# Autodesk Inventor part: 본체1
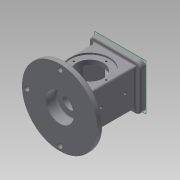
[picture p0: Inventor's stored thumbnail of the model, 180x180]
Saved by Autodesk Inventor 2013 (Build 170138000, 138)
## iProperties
Created: 2019-08
Part Number: 본체1
Material: 일반
Document SubType Name: Modeling
Designer: Administrator
Density: 1 g/cm^3
Author: Administrator
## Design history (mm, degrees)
sketch "스케치6"
  geometry: C1 r 67.5 at (0, 0); 1 further point
  constraints: 1 centre point, 1 coincident
  dimensions: "d14" = 135 diameter of C1
extrude "돌출4" new body sketch "스케치6" distance "d15" = 10; taper "d16" = 0 deg
sketch "스케치7"
  geometry: L1 (-37, -33)-(37, -33); L2 (37, -33)-(37, 33); L3 (37, 33)-(-37, 33); L4 (-37, 33)-(-37, -33); L5 (-37, -33)-(37, 33); L6 (37, -33)-(-37, 33); C1 r 67.5 at (0, 0) reference
  constraints: 12 end point, 2 midpoint, 2 parallel, 1 horizontal, 1 perpendicular
  dimensions: "d17" = 74 distance of L3.end L2.end; "d18" = 66 distance of L2.end L1.end
extrude "돌출5" join sketch "스케치7" distance "d19" = 88; taper "d20" = 0 deg
sketch "스케치8"
  geometry: L1 (-46, -41)-(46, -41); L2 (46, -41)-(46, 41); L3 (46, 41)-(-46, 41); L4 (-46, 41)-(-46, -41); L5 (-46, -41)-(46, 41); L6 (46, -41)-(-46, 41); 1 further point
  constraints: 12 end point, 2 midpoint, 2 parallel, 1 horizontal, 1 perpendicular
  dimensions: "d21" = 92 distance of L3.end L2.end; "d22" = 82 distance of L2.end L1.end
extrude "돌출6" join sketch "스케치8" distance "d23" = 10; taper "d24" = 0 deg
sketch "스케치9"
  geometry: L1 (37, -10)-(37, 44); C1 r 35 at (37, 44)
  constraints: 2 end point, 1 centre point, 1 coincident, 1 vertical
  dimensions: "d25" = 54 distance of L1.start L1.end; "d26" = 70 diameter of C1
extrude "돌출7" cut sketch "스케치9" distance "d27" = 3; taper "d28" = 0 deg
sketch "스케치10"
  geometry: C1 r 35 at (0, 0) reference; C2 r 24 at (0, 0); 1 further point
  constraints: 1 centre point, 1 coincident
  dimensions: "d29" = 48 diameter of C2
extrude "돌출8" cut sketch "스케치10" stored distance "d30" = 3; taper "d31" = 0 deg
sketch "스케치11"
  geometry: C1 r 24 at (37, 44) reference; C2 r 35 at (37, 44); 1 further point
  constraints: 1 centre point, 1 coincident
  dimensions: "d32" = 70 diameter of C2
extrude "돌출9" cut sketch "스케치11" distance "d33" = 3; taper "d34" = 0 deg
sketch "스케치12"
  geometry: L1 (-26, -26)-(26, -26); L2 (26, -26)-(26, 26); L3 (26, 26)-(-26, 26); L4 (-26, 26)-(-26, -26); L5 (-26, -26)-(26, 26); L6 (26, -26)-(-26, 26); 1 further point
  constraints: 12 end point, 2 midpoint, 2 parallel, 1 horizontal, 1 perpendicular
  dimensions: "d35" = 52 distance of L3.end L2.end; "d36" = 52 distance of L2.end L1.end
extrude "돌출10" cut sketch "스케치12" distance "d37" = 8; taper "d38" = 0 deg
sketch "스케치13"
  geometry: L1 (-22, -22)-(22, -22); L2 (22, -22)-(22, 22); L3 (22, 22)-(-22, 22); L4 (-22, 22)-(-22, -22); L5 (-22, -22)-(22, 22); L6 (22, -22)-(-22, 22); 1 further point
  constraints: 12 end point, 2 midpoint, 2 parallel, 1 horizontal, 1 perpendicular
  dimensions: "d39" = 44 distance of L3.end L2.end; "d40" = 44 distance of L2.end L1.end
extrude "돌출11" cut sketch "스케치13" distance "d41" = 74; taper "d42" = 0 deg
sketch "스케치14"
  geometry: C1 r 67.5 at (0, 0) reference; C2 r 25 at (0, 0)
  constraints: 1 centre point, 1 coincident
  dimensions: "d43" = 50 diameter of C2
extrude "돌출12" cut sketch "스케치14" distance "d44" = 18; taper "d45" = 0 deg
sketch "스케치16"
  geometry: L1 (0, 0)-(0, 59); L2 (0, 0)-(-59, 0); L3 (0, 0)-(0, -59); C1 r 67.5 at (0, 0) reference; C2 r 4.5 at (0, 59); C3 r 4.5 at (-59, 0); C4 r 4.5 at (0, -59)
  constraints: 6 end point, 3 centre point, 3 coincident, 2 vertical, 1 horizontal
  dimensions: "d49" = 59 distance of L1.start L1.end; "d50" = 9 diameter of C2; "d54" = 59 distance of L1.start L2.end; "d55" = 9 diameter of C3; "d56" = 59 distance of L1.start L3.end; "d57" = 9 diameter of C4
extrude "돌출14" cut sketch "스케치16" distance "d58" = 18; taper "d59" = 0 deg
sketch "스케치17"
  geometry: C1 r 35 at (0, 0) reference; A1 r 29 centre (0, 0) between (0, 29) and (-29, 0); 3 further points
  constraints: 4 point on circle, 1 centre point, 1 coincident
  dimensions: "d61" = 58 diameter of A1
hole "구멍1" sketch "스케치17" at (0, 29), (-29, 0), (0, -29), (29, 0) diameter "d62" = 3.242; stored, may be unused: countersink angle "d66" = 90 deg, drill point angle "d68" = 118 deg; dims "d63" = 4, "d64" = 4, "d65" = 2, "d67" = 6
sketch "스케치18" dims "d69" = 58
  geometry: C1 r 35 at (0, 0) reference; C2 r 1.621 at (-29, 0) reference; C3 r 1.621 at (0, -29) reference; C4 r 1.621 at (29, 0) reference; 6 further points
  constraints: 4 coincident, 1 vertical alignment, 2 other
hole "구멍2" sketch "스케치18" at (0, 29), (-29, 0), (0, -29), (29, 0) diameter "d70" = 3.242; stored, may be unused: countersink angle "d74" = 90 deg, drill point angle "d76" = 118 deg; dims "d71" = 4, "d72" = 4, "d73" = 2, "d75" = 6
sketch "스케치19"
  geometry: L1 (26, 26)-(26, -26) reference; L2 (26, -26)-(-26, -26) reference; L3 (-26, -26)-(-26, 26) reference; L4 (-26, 26)-(26, 26) reference; L5 (-46, -41)-(46, -41) reference; L6 (46, -41)-(46, 41) reference; L7 (46, 41)-(-46, 41) reference; L8 (-46, 41)-(-46, -41) reference; 1 further point
sketch "스케치20"
  geometry: C1 r 25 at (0, 0) reference; C2 r 12.5 at (0, 0)
  constraints: 1 centre point, 1 coincident
  dimensions: "d77" = 25 diameter of C2
extrude "돌출15" cut sketch "스케치20" distance "d78" = 18; taper "d79" = 0 deg
sketch "스케치21"
  geometry: L1 (26, 26)-(26, -26) reference; L2 (26, -26)-(-26, -26) reference; L3 (-26, -26)-(-26, 26) reference; L4 (-26, 26)-(26, 26) reference; L5 (-46, -41)-(46, -41) reference; L6 (46, -41)-(46, 41) reference; L7 (46, 41)-(-46, 41) reference; L8 (-46, 41)-(-46, -41) reference; 1 further point
fillet "모깎기1" dims "d80" = 10
sketch "스케치22"
  geometry: A1 r 10 centre (36, 31) between (46, 31) and (36, 41) reference; A2 r 10 centre (-36, 31) between (-36, 41) and (-46, 31) reference; A3 r 10 centre (-36, -31) between (-46, -31) and (-36, -41) reference; A4 r 10 centre (36, -31) between (36, -41) and (46, -31) reference; 1 further point
hole "구멍3" sketch "스케치22" at (-36, 31), (-36, -31), (36, -31), (36, 31) diameter "d81" = 3.242; stored, may be unused: countersink angle "d85" = 90 deg, drill point angle "d87" = 118 deg; dims "d82" = 4, "d83" = 4, "d84" = 2, "d86" = 6
sketch "스케치23"
  geometry: L1 (33, -10)-(33, 27); L2 (33, 27)-(33, 70)
  constraints: 4 end point, 2 vertical
  dimensions: "d88" = 37 distance of L1.start L1.end; "d89" = 43 distance of L1.end L2.end
hole "구멍4" sketch "스케치23" at (33, 70), (33, 27) diameter "d90" = 4.917; stored, may be unused: countersink angle "d94" = 90 deg, drill point angle "d96" = 118 deg; dims "d91" = 30, "d92" = 4, "d93" = 2, "d95" = 30
sketch "스케치24"
  geometry: C1 r 67.5 at (0, 0) reference; C2 r 59 at (0, 0)
  constraints: 1 centre point, 1 coincident, 1 other
  dimensions: "d97" = 118 diameter of C2
fillet "모깎기2" dims "d98" = 3
fillet "모깎기3" dims "d99" = 3
fillet "모깎기4" dims "d100" = 3
feature "엠보싱1" dims "d104" = 0.5, "d105" = 0
fillet "모깎기5" dims "d106" = 3
fillet "모깎기6" dims "d107" = 3
fillet "모깎기7" dims "d108" = 3
chamfer "모따기2" distance "d109" = 1; stored, may be unused: second distance "d110" = 2, angle "d111" = 45 deg
fillet "모깎기8" dims "d112" = 3
fillet "모깎기9" dims "d113" = 3
fillet "모깎기10" dims "d114" = 3
node "솔리드2"
